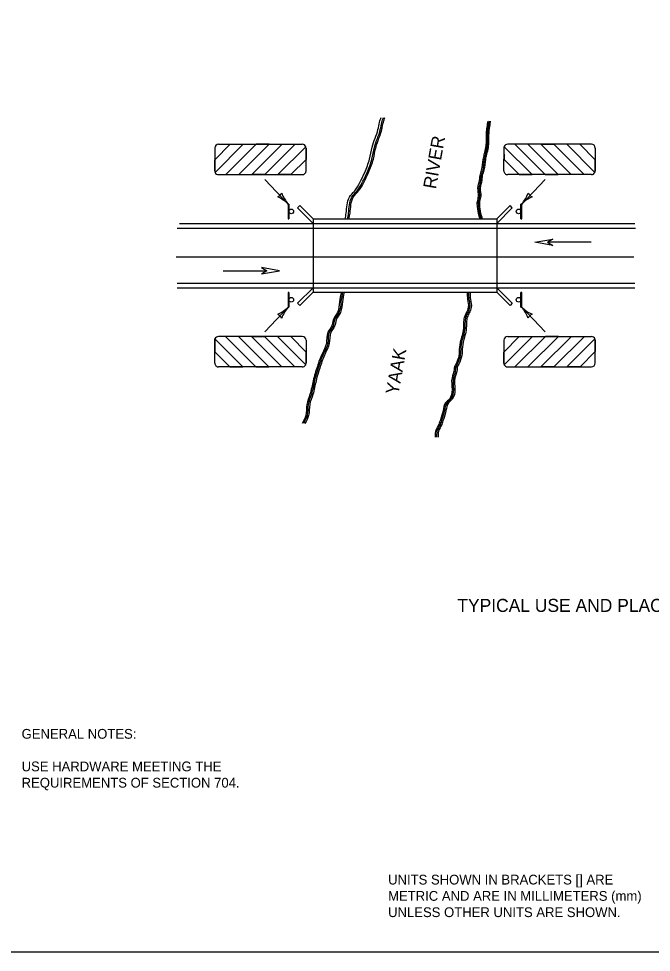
# Model space of a CAD drawing. Extents: x 49991.4 to 50021, y 49987.6 to 50011.4.
# Drawn here: x 50010.3 to 50014.19, y 49987.8 to 49993.53 of the extents above; entities that cross this region are included whole.
import ezdxf

# ---------------------------------------------------------------- set-up
doc = ezdxf.new("R2010")
doc.units = 0
for name, color, linetype in [('Level 1', 7, 'Continuous'), ('Level 2', 7, 'Continuous'), ('Level 3', 7, 'Continuous'), ('Level 4', 7, 'Continuous'), ('Level 5', 7, 'Continuous')]:
    doc.layers.add(name, color=color, linetype=linetype)

msp = doc.modelspace()

# ---------------------------------------------------------------- linework, layer by layer
at = {"layer": 'Level 1'}
for p, q in [((50011.5071, 49992.6638), (50011.6013, 49992.759)), ((50011.5071, 49992.7357), (50011.5071, 49992.5955)), ((50011.6821, 49992.759), (50011.5092, 49992.5861)), ((50011.5304, 49992.759), (50012.0441, 49992.759)), ((50011.7619, 49992.759), (50011.5752, 49992.5722)), ((50011.6013, 49992.759), (50011.6821, 49992.759)), ((50011.6549, 49992.5722), (50011.8416, 49992.759)), ((50011.7347, 49992.5722), (50011.9216, 49992.759)), ((50011.8416, 49992.759), (50011.7619, 49992.759)), ((50012.0012, 49992.759), (50011.8146, 49992.5722)), ((50011.8943, 49992.5722), (50012.0659, 49992.7439)), ((50011.9216, 49992.759), (50012.0012, 49992.759)), ((50012.0674, 49992.7357), (50012.0674, 49992.6662)), ((50012.0674, 49992.5955), (50012.0674, 49992.7352)), ((50013.2815, 49992.5957), (50013.283, 49992.744)), ((50013.2815, 49992.7358), (50013.2822, 49992.6649)), ((50013.4546, 49992.5723), (50013.283, 49992.744)), ((50013.8184, 49992.7591), (50013.3048, 49992.7591)), ((50013.4274, 49992.7591), (50013.3477, 49992.7591)), ((50013.3477, 49992.7591), (50013.5343, 49992.5723)), ((50013.6142, 49992.5723), (50013.4274, 49992.7591)), ((50013.694, 49992.5723), (50013.5073, 49992.7591)), ((50013.5073, 49992.7591), (50013.587, 49992.7591)), ((50013.587, 49992.7591), (50013.7737, 49992.5723)), ((50013.7476, 49992.7591), (50013.6668, 49992.7591)), ((50013.6668, 49992.7591), (50013.8397, 49992.5862)), ((50013.8418, 49992.6639), (50013.7476, 49992.7591)), ((50013.8418, 49992.7358), (50013.8418, 49992.5957)), ((50011.5071, 49992.5956), (50011.5071, 49992.6638)), ((50012.0674, 49992.6662), (50011.9746, 49992.5722)), ((50013.2822, 49992.6649), (50013.3743, 49992.5723)), ((50013.8418, 49992.5957), (50013.8418, 49992.6639)), ((50011.5071, 49992.5956), (50011.5071, 49992.5956)), ((50013.8418, 49992.5957), (50013.8418, 49992.5957)), ((50011.5305, 49992.5722), (50012.0441, 49992.5722)), ((50011.5752, 49992.5722), (50011.6549, 49992.5722)), ((50011.8146, 49992.5722), (50011.7347, 49992.5722)), ((50011.8946, 49992.5722), (50011.8943, 49992.5722)), ((50011.9746, 49992.5722), (50011.8946, 49992.5722)), ((50013.8184, 49992.5723), (50013.3048, 49992.5723)), ((50013.3743, 49992.5723), (50013.4543, 49992.5723)), ((50013.4543, 49992.5723), (50013.4546, 49992.5723)), ((50013.5343, 49992.5723), (50013.6142, 49992.5723)), ((50013.7737, 49992.5723), (50013.694, 49992.5723)), ((50011.9582, 49992.3921), (50011.9582, 49992.3012)), ((50011.9627, 49992.3921), (50011.9582, 49992.3921)), ((50011.9627, 49992.3921), (50011.9627, 49992.3012)), ((50012.0156, 49992.3679), (50012.0298, 49992.3821)), ((50012.111, 49992.2725), (50012.0156, 49992.3679)), ((50012.0298, 49992.3821), (50012.111, 49992.3009)), ((50013.319, 49992.3821), (50013.2377, 49992.3009)), ((50013.2377, 49992.2725), (50013.3331, 49992.3679)), ((50013.3331, 49992.3679), (50013.319, 49992.3821)), ((50013.3906, 49992.392), (50013.386, 49992.392)), ((50013.386, 49992.3011), (50013.386, 49992.392)), ((50013.3906, 49992.3011), (50013.3906, 49992.392)), ((50011.9582, 49992.3012), (50011.9627, 49992.3012)), ((50012.111, 49992.3009), (50013.2377, 49992.3009)), ((50012.111, 49992.3009), (50012.111, 49991.85)), ((50012.111, 49992.2725), (50013.2377, 49992.2725)), ((50013.2377, 49992.3009), (50013.2377, 49991.85)), ((50013.386, 49992.3011), (50013.3906, 49992.3011)), ((50011.2774, 49992.2442), (50014.0883, 49992.2442)), ((50013.8166, 49992.1574), (50013.5482, 49992.1574)), ((50011.5594, 49991.9828), (50011.8278, 49991.9828)), ((50011.2774, 49991.9067), (50014.0848, 49991.9067)), ((50011.9581, 49991.8496), (50011.9581, 49991.7587)), ((50011.9627, 49991.8496), (50011.9581, 49991.8496)), ((50011.9627, 49991.8496), (50011.9627, 49991.7587)), ((50012.111, 49991.8783), (50012.0156, 49991.7829)), ((50012.0298, 49991.7687), (50012.111, 49991.85)), ((50012.111, 49991.8783), (50013.2377, 49991.8783)), ((50012.111, 49991.85), (50013.2377, 49991.85)), ((50013.2377, 49991.8783), (50013.3331, 49991.7829)), ((50013.319, 49991.7687), (50013.2377, 49991.85)), ((50013.3906, 49991.8497), (50013.3861, 49991.8497)), ((50013.3861, 49991.7588), (50013.3861, 49991.8497)), ((50013.3906, 49991.7588), (50013.3906, 49991.8497)), ((50011.9581, 49991.7587), (50011.9627, 49991.7587)), ((50012.0156, 49991.7829), (50012.0298, 49991.7687)), ((50013.3331, 49991.7829), (50013.319, 49991.7687)), ((50013.3861, 49991.7588), (50013.3906, 49991.7588)), ((50011.5071, 49991.4152), (50011.5086, 49991.5635)), ((50011.6802, 49991.3918), (50011.5086, 49991.5635)), ((50012.0441, 49991.5786), (50011.5304, 49991.5786)), ((50011.653, 49991.5786), (50011.5733, 49991.5786)), ((50011.5733, 49991.5786), (50011.7599, 49991.3918)), ((50011.8398, 49991.3918), (50011.653, 49991.5786)), ((50011.9196, 49991.3918), (50011.7329, 49991.5786)), ((50011.7329, 49991.5786), (50011.8126, 49991.5786)), ((50011.8126, 49991.5786), (50011.9993, 49991.3918)), ((50011.9732, 49991.5786), (50011.8924, 49991.5786)), ((50011.8924, 49991.5786), (50012.0653, 49991.4057)), ((50012.0674, 49991.4834), (50011.9732, 49991.5786)), ((50013.2814, 49991.4835), (50013.3756, 49991.5787)), ((50013.4564, 49991.5787), (50013.2835, 49991.4058)), ((50013.3048, 49991.5787), (50013.8184, 49991.5787)), ((50013.5362, 49991.5787), (50013.3495, 49991.3919)), ((50013.3756, 49991.5787), (50013.4564, 49991.5787)), ((50013.4292, 49991.3919), (50013.6159, 49991.5787)), ((50013.509, 49991.3919), (50013.6959, 49991.5787)), ((50013.6159, 49991.5787), (50013.5362, 49991.5787)), ((50013.7755, 49991.5787), (50013.5889, 49991.3919)), ((50013.6686, 49991.3919), (50013.8402, 49991.5636)), ((50013.6959, 49991.5787), (50013.7755, 49991.5787)), ((50011.5071, 49991.5553), (50011.5078, 49991.4844)), ((50012.0674, 49991.5553), (50012.0674, 49991.4152)), ((50013.2814, 49991.5554), (50013.2814, 49991.4152)), ((50013.8418, 49991.5554), (50013.8417, 49991.4859)), ((50013.8417, 49991.4153), (50013.8417, 49991.5549)), ((50011.5078, 49991.4844), (50011.5999, 49991.3918)), ((50012.0674, 49991.4152), (50012.0674, 49991.4834)), ((50013.2814, 49991.4153), (50013.2814, 49991.4835)), ((50013.8417, 49991.4859), (50013.7489, 49991.3919)), ((50012.044, 49991.3918), (50011.5304, 49991.3918)), ((50011.5999, 49991.3918), (50011.6799, 49991.3918)), ((50011.6799, 49991.3918), (50011.6802, 49991.3918)), ((50011.7599, 49991.3918), (50011.8398, 49991.3918)), ((50011.9993, 49991.3918), (50011.9196, 49991.3918)), ((50012.0674, 49991.4152), (50012.0674, 49991.4152)), ((50013.2814, 49991.4153), (50013.2814, 49991.4153)), ((50013.3048, 49991.3919), (50013.8184, 49991.3919)), ((50013.3495, 49991.3919), (50013.4292, 49991.3919)), ((50013.5889, 49991.3919), (50013.509, 49991.3919)), ((50013.6689, 49991.3919), (50013.6686, 49991.3919)), ((50013.7489, 49991.3919), (50013.6689, 49991.3919))]:
    msp.add_line(p, q, dxfattribs=at)
for points in [[(49999.3835, 49998.9992), (50016.7501, 49998.9992), (50016.7501, 49987.7988), (49999.3835, 49987.7988)], [(50013.5823, 49992.1377), (50013.4706, 49992.1574), (50013.5823, 49992.1772), (50013.5483, 49992.1574)], [(50011.7937, 49991.9631), (50011.9054, 49991.9828), (50011.7937, 49992.0026), (50011.8277, 49991.9828)]]:
    msp.add_lwpolyline(points, close=True, dxfattribs=at)
for centre in [(50011.9769, 49992.3466), (50013.3718, 49992.3466), (50011.9769, 49991.8042), (50013.3718, 49991.8042)]:
    msp.add_circle(centre, 0.0142, dxfattribs=at)
for centre, start, end in [((50011.5304, 49992.7357), 90, 180), ((50012.0441, 49992.7357), 20.69724, 90), ((50012.0441, 49992.7357), 0, 20.69828), ((50013.3048, 49992.7358), 159.30172, 180), ((50013.3048, 49992.7358), 90, 159.30276), ((50013.8184, 49992.7358), 0, 90), ((50011.5305, 49992.5956), 180, 204.09678), ((50012.0441, 49992.5955), 270, 0), ((50013.3048, 49992.5956), 179.86731, 270), ((50013.8184, 49992.5957), 335.90322, 0), ((50011.5305, 49992.5955), 203.96062, 270), ((50013.8184, 49992.5956), 270, 336.06412), ((50011.5304, 49991.5553), 159.30172, 180), ((50011.5304, 49991.5553), 90, 159.30276), ((50012.0441, 49991.5553), 0, 90), ((50013.3048, 49991.5554), 90, 180), ((50013.8184, 49991.5554), 20.69724, 90), ((50013.8184, 49991.5554), 0, 20.69828), ((50011.5304, 49991.4151), 179.86731, 270), ((50012.044, 49991.4151), 270, 336.11546), ((50012.044, 49991.4152), 335.90322, 0), ((50013.3048, 49991.4153), 180, 204.09678), ((50013.3048, 49991.4153), 203.96062, 270), ((50013.8184, 49991.4153), 270, 360)]:
    msp.add_arc(centre, 0.0233, start, end, dxfattribs=at)
for points in [[(50012.3075, 49992.3009), (50012.3139, 49992.3361), (50012.3334, 49992.4335), (50012.3659, 49992.4725), (50012.3983, 49992.5244), (50012.4275, 49992.5861), (50012.4567, 49992.6672), (50012.4729, 49992.7419), (50012.5087, 49992.849), (50012.5184, 49992.8943), (50012.5282, 49992.9236)], [(50012.3221, 49992.3009), (50012.3284, 49992.3357), (50012.3479, 49992.4332), (50012.3804, 49992.472), (50012.4128, 49992.524), (50012.4421, 49992.5857), (50012.4712, 49992.6668), (50012.4874, 49992.7415), (50012.5231, 49992.8485), (50012.5329, 49992.894), (50012.5427, 49992.9232)], [(50012.3313, 49992.3009), (50012.3377, 49992.3365), (50012.3573, 49992.4339), (50012.3897, 49992.4728), (50012.4221, 49992.5247), (50012.4513, 49992.5864), (50012.4806, 49992.6675), (50012.4968, 49992.7422), (50012.5325, 49992.8492), (50012.5422, 49992.8947), (50012.5519, 49992.9239)], [(50013.1348, 49992.3009), (50013.1289, 49992.3203), (50013.1192, 49992.3755), (50013.1192, 49992.408), (50013.1257, 49992.4404), (50013.1225, 49992.489), (50013.1322, 49992.5377), (50013.1354, 49992.567), (50013.1451, 49992.5995), (50013.1549, 49992.6644), (50013.1614, 49992.6968), (50013.1711, 49992.739), (50013.1744, 49992.778), (50013.1744, 49992.8168), (50013.1776, 49992.8558), (50013.1809, 49992.8786), (50013.1841, 49992.9012)], [(50013.1432, 49992.3009), (50013.1372, 49992.3208), (50013.1275, 49992.376), (50013.1275, 49992.4085), (50013.134, 49992.441), (50013.1307, 49992.4896), (50013.1405, 49992.5383), (50013.1437, 49992.5675), (50013.1534, 49992.6), (50013.1631, 49992.6649), (50013.1697, 49992.6973), (50013.1794, 49992.7395), (50013.1827, 49992.7785), (50013.1827, 49992.8174), (50013.1859, 49992.8563), (50013.1891, 49992.8791), (50013.1924, 49992.9018)], [(50013.1505, 49992.3009), (50013.1444, 49992.3203), (50013.1347, 49992.3755), (50013.1347, 49992.408), (50013.1412, 49992.4404), (50013.1379, 49992.489), (50013.1477, 49992.5377), (50013.1509, 49992.567), (50013.1606, 49992.5995), (50013.1703, 49992.6644), (50013.1769, 49992.6968), (50013.1866, 49992.739), (50013.1899, 49992.778), (50013.1899, 49992.8168), (50013.1931, 49992.8558), (50013.1963, 49992.8786), (50013.1996, 49992.9012)], [(50012.2828, 49991.85), (50012.2731, 49991.7913), (50012.2602, 49991.7263), (50012.2341, 49991.6809), (50012.2244, 49991.642), (50012.2017, 49991.6062), (50012.192, 49991.5349), (50012.1661, 49991.4732), (50012.1369, 49991.3953), (50012.1109, 49991.3077), (50012.0914, 49991.2233), (50012.0719, 49991.1616), (50012.0654, 49991.0934), (50012.0427, 49991.0448)], [(50012.2917, 49991.85), (50012.2819, 49991.7918), (50012.2689, 49991.7268), (50012.2429, 49991.6815), (50012.2332, 49991.6425), (50012.2105, 49991.6068), (50012.2007, 49991.5354), (50012.1747, 49991.4738), (50012.1456, 49991.3958), (50012.1196, 49991.3082), (50012.1001, 49991.2238), (50012.0806, 49991.1622), (50012.0741, 49991.094), (50012.0515, 49991.0454)], [(50012.3009, 49991.85), (50012.2911, 49991.7913), (50012.2782, 49991.7263), (50012.2522, 49991.6809), (50012.2425, 49991.642), (50012.2198, 49991.6062), (50012.21, 49991.5349), (50012.1841, 49991.4732), (50012.1549, 49991.3953), (50012.1289, 49991.3077), (50012.1094, 49991.2233), (50012.09, 49991.1616), (50012.0835, 49991.0934), (50012.0608, 49991.0448)], [(50013.0572, 49991.85), (50013.0572, 49991.8176), (50013.0637, 49991.769), (50013.054, 49991.73), (50013.041, 49991.704), (50013.0345, 49991.6716), (50013.0313, 49991.6164), (50013.0216, 49991.5742), (50013.0086, 49991.5126), (50013.0054, 49991.4606), (50012.9858, 49991.4087), (50012.9761, 49991.3794), (50012.9761, 49991.3762), (50012.9631, 49991.3243), (50012.9631, 49991.2529), (50012.9469, 49991.1945), (50012.9242, 49991.1717), (50012.9079, 49991.1231), (50012.8917, 49991.068), (50012.882, 49991.0387), (50012.8625, 49990.9965), (50012.8593, 49990.9608)], [(50013.0657, 49991.85), (50013.0657, 49991.8182), (50013.0721, 49991.7695), (50013.0624, 49991.7306), (50013.0495, 49991.7046), (50013.043, 49991.6722), (50013.0397, 49991.617), (50013.0299, 49991.5748), (50013.017, 49991.5132), (50013.0137, 49991.4612), (50012.9943, 49991.4093), (50012.9846, 49991.3801), (50012.9846, 49991.3768), (50012.9716, 49991.3249), (50012.9716, 49991.2535), (50012.9553, 49991.1951), (50012.9326, 49991.1724), (50012.9163, 49991.1237), (50012.9001, 49991.0686), (50012.8904, 49991.0393), (50012.8709, 49990.9971), (50012.8677, 49990.9614)], [(50013.0657, 49991.85), (50013.0657, 49991.8182), (50013.0721, 49991.7695), (50013.0624, 49991.7306), (50013.0495, 49991.7046), (50013.043, 49991.6722), (50013.0397, 49991.617), (50013.0299, 49991.5748), (50013.017, 49991.5132), (50013.0137, 49991.4612), (50012.9943, 49991.4093), (50012.9846, 49991.3801), (50012.9846, 49991.3768), (50012.9716, 49991.3249), (50012.9716, 49991.2535), (50012.9553, 49991.1951), (50012.9326, 49991.1724), (50012.9163, 49991.1237), (50012.9001, 49991.0686), (50012.8904, 49991.0393), (50012.8709, 49990.9971), (50012.8677, 49990.9614)], [(50013.0755, 49991.85), (50013.0755, 49991.8182), (50013.0819, 49991.7695), (50013.0722, 49991.7306), (50013.0593, 49991.7046), (50013.0528, 49991.6722), (50013.0495, 49991.617), (50013.0397, 49991.5748), (50013.0268, 49991.5132), (50013.0235, 49991.4612), (50013.004, 49991.4093), (50012.9943, 49991.3801), (50012.9943, 49991.3768), (50012.9813, 49991.3249), (50012.9813, 49991.2535), (50012.9651, 49991.1951), (50012.9425, 49991.1724), (50012.9262, 49991.1237), (50012.91, 49991.0686), (50012.9002, 49991.0393), (50012.8807, 49990.9971), (50012.8775, 49990.9614)]]:
    msp.add_spline(points, degree=3, dxfattribs=at)
at = {"layer": 'Level 3'}
for p, q in [((50011.8148, 49992.5432), (50011.9582, 49992.3921)), ((50013.5341, 49992.5433), (50013.3906, 49992.392)), ((50011.8148, 49991.6077), (50011.9581, 49991.7587)), ((50013.5341, 49991.6078), (50013.3906, 49991.7588))]:
    msp.add_line(p, q, dxfattribs=at)
for centre, radius, start, end in [((50011.87, 49992.4852), 0.0548, 295.58119, 331.30356), ((50011.7971, 49992.2237), 0.233, 46.26969, 65.51954), ((50012.1258, 49992.5382), 0.2223, 200.89839, 221.08189), ((50013.2137, 49992.5437), 0.233, 319.37811, 338.62796), ((50013.5456, 49992.2326), 0.2223, 114.00681, 134.19032), ((50013.4788, 49992.4851), 0.0548, 208.68962, 244.41198), ((50011.8031, 49991.9181), 0.2223, 294.0077, 314.19121), ((50012.1349, 49991.607), 0.233, 139.379, 158.62885), ((50013.223, 49991.6126), 0.2223, 20.92109, 41.10459), ((50013.5516, 49991.9272), 0.233, 226.29239, 245.54224), ((50011.8699, 49991.6656), 0.0548, 28.69051, 64.41287), ((50013.4788, 49991.6657), 0.0548, 115.60389, 151.32626)]:
    msp.add_arc(centre, radius, start, end, dxfattribs=at)
at = {"layer": 'Level 4'}
for p, q in [((50011.29, 49992.2725), (50012.111, 49992.2725)), ((50013.2377, 49992.2725), (50014.0848, 49992.2725)), ((50011.2774, 49991.8783), (50012.111, 49991.8783)), ((50013.2377, 49991.8783), (50014.0848, 49991.8783))]:
    msp.add_line(p, q, dxfattribs=at)
at = {"layer": 'Level 5'}
msp.add_line((50011.2711, 49992.0669), (50014.0785, 49992.0669), dxfattribs=at)

# ---------------------------------------------------------------- texts
at = {"layer": 'Level 2'}
for s, rotation, p in [('RIVER', 79.91539, (50012.8641, 49992.4806)), ('YAAK', 79.92188, (50012.6338, 49991.2178))]:
    msp.add_text(s, height=0.08, rotation=rotation, dxfattribs=at).set_placement(p)
for s, height, p in [('TYPICAL USE AND PLACEMENT', 0.08, (50012.9958, 49989.8882)), ('GENERAL NOTES:', 0.06, (50010.3222, 49989.1099)), ('USE HARDWARE MEETING THE ', 0.06, (50010.3222, 49988.9099)), ('REQUIREMENTS OF SECTION 704.', 0.06, (50010.3222, 49988.8099)), ('UNITS SHOWN IN BRACKETS [] ARE ', 0.06, (50012.571, 49988.2151)), ('METRIC AND ARE IN MILLIMETERS (mm) ', 0.06, (50012.571, 49988.1151)), ('UNLESS OTHER UNITS ARE SHOWN.', 0.06, (50012.571, 49988.0151))]:
    msp.add_text(s, height=height, dxfattribs=at).set_placement(p)

doc.saveas('drawing.dxf')
